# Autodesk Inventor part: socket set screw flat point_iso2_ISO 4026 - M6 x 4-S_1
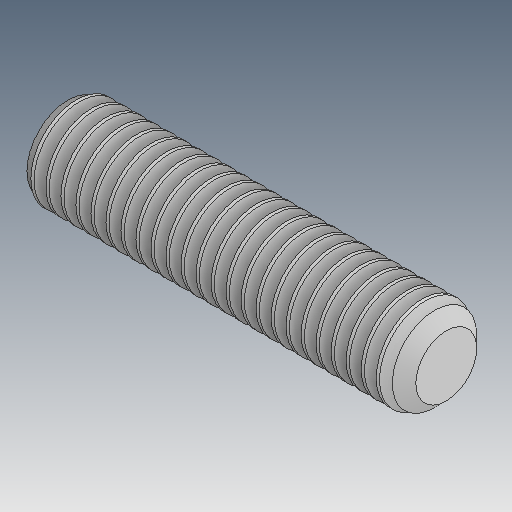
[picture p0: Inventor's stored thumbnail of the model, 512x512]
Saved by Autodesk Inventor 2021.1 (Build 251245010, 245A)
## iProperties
Created: 2019-04
Part Number: socket set screw flat point_iso2_ISO 4026 - M6 x 4-S_1
Material: Ogólny
Document SubType Name: Modeling
Designer: user
Density: 1 g/cm^3
Appearance: Domyślna
Author: user
Revision Number: ÈÎºÎ
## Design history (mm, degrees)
feature "ÊäÈë1"
node "Bryła1"
